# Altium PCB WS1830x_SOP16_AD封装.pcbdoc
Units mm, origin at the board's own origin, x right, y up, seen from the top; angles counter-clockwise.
Board outline 34.4 x 35.91 mm, 2 copper layers (Top Layer, Bottom Layer); 1 components, 0 nets, 16 pads, 0 vias.
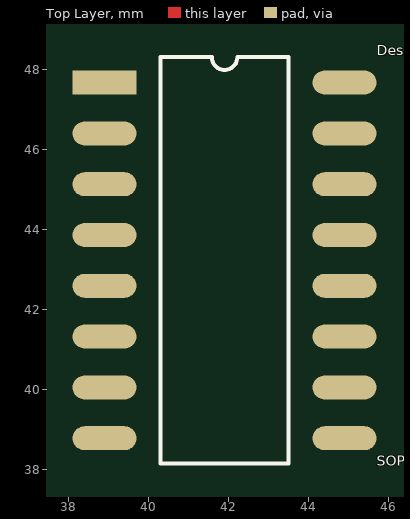
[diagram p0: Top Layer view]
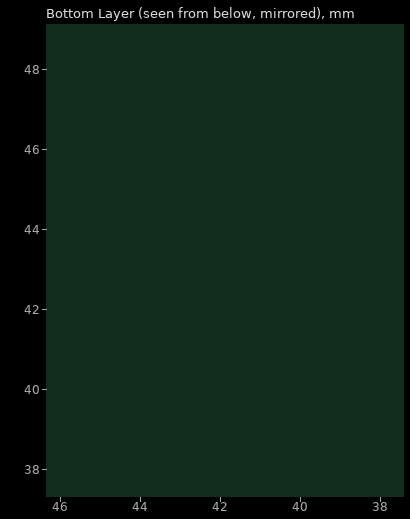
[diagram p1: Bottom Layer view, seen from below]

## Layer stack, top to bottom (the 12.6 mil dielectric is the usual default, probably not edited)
Top Layer: signal copper (thickness not stored)
Dielectric: dielectric 0.32, FR-4, Dk 4.8
Bottom Layer: signal copper (thickness not stored)

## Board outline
59.797,25.4 25.4,25.4 25.4,61.314 59.797,61.314

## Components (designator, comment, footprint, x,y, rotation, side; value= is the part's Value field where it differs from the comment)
Designator? "SOP16" SOP16 41.9,43.23 r0 top

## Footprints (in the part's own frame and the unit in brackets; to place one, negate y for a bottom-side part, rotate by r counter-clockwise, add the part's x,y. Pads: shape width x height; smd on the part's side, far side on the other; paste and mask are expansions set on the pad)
SOP16 [mm]
  rect 1.6x0.6 smd paste+0 mask+0.102: 1(-3,4.445)
  oval 1.6x0.6 smd paste+0 mask+0.102: 2(-3,3.175) 3(-3,1.905) 4(-3,0.635) 5(-3,-0.635) 6(-3,-1.905) 7(-3,-3.175) 8(-3,-4.445) 9(3,-4.445) 10(3,-3.175) 11(3,-1.905) 12(3,-0.635) 13(3,0.635) 14(3,1.905) 15(3,3.175) 16(3,4.445)
  silkscreen extent -1.6,-5.08 1.6,5.08

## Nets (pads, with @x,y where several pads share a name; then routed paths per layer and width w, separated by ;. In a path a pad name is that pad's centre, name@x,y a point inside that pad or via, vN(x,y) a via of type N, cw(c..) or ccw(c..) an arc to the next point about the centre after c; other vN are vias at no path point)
pads on no net: Designator?.1 Designator?.2 Designator?.3 Designator?.4 Designator?.5 Designator?.6 Designator?.7 Designator?.8 Designator?.9 Designator?.10 Designator?.11 Designator?.12 Designator?.13 Designator?.14 Designator?.15 Designator?.16

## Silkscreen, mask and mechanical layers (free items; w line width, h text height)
Document:
  lines w0.003: 42.598,43.357 42.599,43.357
